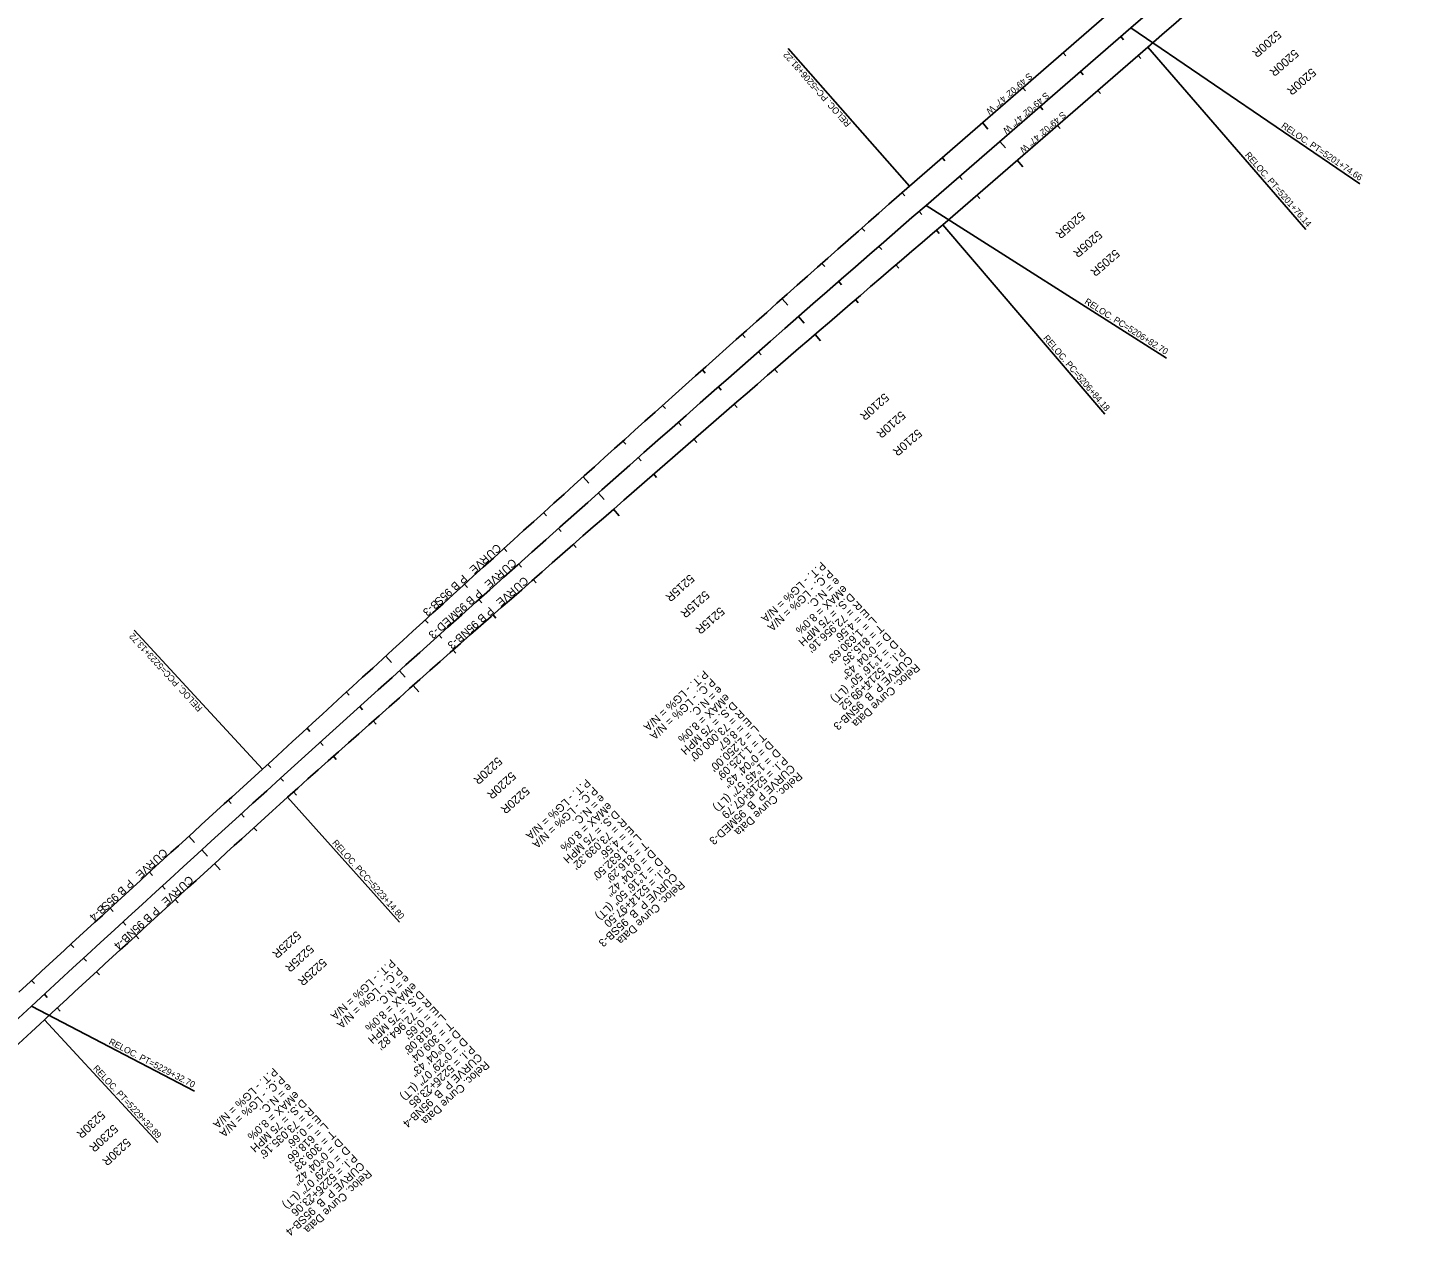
# Model space of a CAD drawing. Extents: x 2161211 to 2175594, y 601812 to 617732.
# Drawn here: x 2167933 to 2170529, y 609442 to 611719 of the extents above; entities that cross this region are included whole.
import ezdxf

# ---------------------------------------------------------------- set-up
doc = ezdxf.new("R2010")
doc.units = 0
for name, color, linetype in [('RD_HC_CL_Rel', 7, 'Continuous'), ('RD_HC_Data_Rel', 7, 'Continuous'), ('RD_HC_Data_Tic_Rel', 7, 'Continuous'), ('RD_HC_TX_Rel_Sta50', 7, 'Continuous')]:
    doc.layers.add(name, color=color, linetype=linetype)

msp = doc.modelspace()

# ---------------------------------------------------------------- linework, layer by layer
at = {"layer": 'RD_HC_CL_Rel'}
for p, q in [((2169968.3, 611754.8), (2169584.6, 611421.8)), ((2169999.7, 611718.5), (2169616.1, 611385.5)), ((2170031.2, 611682.3), (2169647.5, 611349.3)), ((2167939.8, 609884.8), (2165490.6, 607623.3)), ((2167963.7, 609859.1), (2165514.5, 607597.4))]:
    msp.add_line(p, q, dxfattribs=at)
for centre, radius, start, end in [((2122152.2, 666851.2), 73000, 310.953509, 312.719474), ((2122152.2, 666851.2), 73048, 310.953509, 312.719474), ((2217890.3, 556637.7), 73039.3, 131.404137, 132.684757), ((2217463.6, 556252.9), 73000, 130.953509, 132.719474), ((2217031.5, 555875.3), 72956.2, 130.502821, 131.783426), ((2217463.6, 556252.9), 73035.2, 132.23405, 132.719387), ((2217463.6, 556252.9), 72964.8, 132.234034, 132.719387)]:
    msp.add_arc(centre, radius, start, end, dxfattribs=at)
at = {"layer": 'RD_HC_Data_Rel'}
for p, q in [((2169999.7, 611718.5), (2170428.7, 611426.1)), ((2169584.6, 611421.8), (2169357.3, 611679.5)), ((2170031.2, 611682.3), (2170327.7, 611340.6)), ((2169616.1, 611385.5), (2170066.3, 611099.2)), ((2169647.5, 611349.3), (2169950.9, 610994.1)), ((2168372.3, 610328.5), (2168131.9, 610589.1)), ((2168419.6, 610276.4), (2168628.9, 610042.2)), ((2167939.8, 609884.8), (2168244.9, 609725.3)), ((2167963.7, 609859.1), (2168176.1, 609629.1))]:
    msp.add_line(p, q, dxfattribs=at)
at = {"layer": 'RD_HC_Data_Tic_Rel'}
for p, q in [((2169980.6, 611701.9), (2169985.9, 611695.9)), ((2169872.5, 611671.6), (2169877.8, 611665.6)), ((2170013.2, 611666.6), (2170018.4, 611660.6)), ((2169905.1, 611636.4), (2169910.3, 611630.3)), ((2169797, 611606.1), (2169802.2, 611600.1)), ((2169937.7, 611601.1), (2169942.9, 611595)), ((2169829.6, 611570.8), (2169834.8, 611564.8)), ((2169721.5, 611540.6), (2169731.9, 611528.5)), ((2169862.1, 611535.5), (2169867.4, 611529.5)), ((2169754, 611505.3), (2169764.5, 611493.2)), ((2169645.9, 611475), (2169651.2, 611469)), ((2169786.6, 611470), (2169797.1, 611457.9)), ((2169678.5, 611439.7), (2169683.8, 611433.7)), ((2169570.5, 611409.4), (2169575.8, 611403.4)), ((2169711.1, 611404.4), (2169716.3, 611398.4)), ((2169603, 611374.2), (2169608.2, 611368.1)), ((2169495.6, 611343.1), (2169500.9, 611337.2)), ((2169635.5, 611339), (2169640.7, 611332.9)), ((2169527.5, 611308.6), (2169532.8, 611302.5)), ((2169420.7, 611276.8), (2169426, 611270.9)), ((2169559.5, 611274), (2169564.7, 611267.9)), ((2169452.2, 611242.9), (2169457.4, 611236.8)), ((2169346, 611210.4), (2169356.6, 611198.5)), ((2169483.6, 611208.9), (2169488.8, 611202.8)), ((2169376.9, 611177), (2169387.4, 611165)), ((2169271.3, 611143.9), (2169276.6, 611137.9)), ((2169407.8, 611143.6), (2169418.3, 611131.5)), ((2169301.7, 611111.1), (2169307, 611105.1)), ((2169196.7, 611077.3), (2169202, 611071.3)), ((2169332.1, 611078.3), (2169337.3, 611072.3)), ((2169226.6, 611045.1), (2169231.9, 611039.1)), ((2169122.2, 611010.6), (2169127.6, 611004.6)), ((2169256.5, 611012.9), (2169261.7, 611006.8)), ((2169151.6, 610979), (2169156.9, 610973)), ((2169047.8, 610943.8), (2169053.2, 610937.8)), ((2169181, 610947.3), (2169186.2, 610941.3)), ((2169076.6, 610912.7), (2169081.9, 610906.7)), ((2168973.5, 610876.8), (2168984.2, 610865)), ((2169105.5, 610881.7), (2169110.8, 610875.7)), ((2169001.8, 610846.4), (2169012.4, 610834.4)), ((2168899.3, 610809.8), (2168904.7, 610803.9)), ((2169030.2, 610816), (2169040.7, 610803.9)), ((2168927.1, 610779.9), (2168932.4, 610774)), ((2168825.2, 610742.7), (2168830.5, 610736.8)), ((2168954.9, 610750.1), (2168960.2, 610744.1)), ((2168852.4, 610713.4), (2168857.7, 610707.4)), ((2168879.7, 610684.2), (2168885, 610678.1)), ((2168751.1, 610675.5), (2168756.5, 610669.5)), ((2168777.9, 610646.8), (2168783.2, 610640.8)), ((2168677.2, 610608.1), (2168682.6, 610602.2)), ((2168804.7, 610618.1), (2168809.9, 610612.1)), ((2168703.4, 610580), (2168708.7, 610574.1)), ((2168729.7, 610551.9), (2168735, 610546)), ((2168603.4, 610540.7), (2168614.2, 610528.9)), ((2168629, 610513.2), (2168639.7, 610501.3)), ((2168529.6, 610473.2), (2168535, 610467.3)), ((2168654.8, 610485.7), (2168665.4, 610473.7)), ((2168554.7, 610446.2), (2168560.1, 610440.3)), ((2168580, 610419.3), (2168585.3, 610413.3)), ((2168455.9, 610405.5), (2168461.4, 610399.6)), ((2168480.5, 610379.2), (2168485.9, 610373.2)), ((2168505.2, 610352.9), (2168510.6, 610346.9)), ((2168382.4, 610337.8), (2168387.8, 610331.9)), ((2168406.4, 610312), (2168411.8, 610306.1)), ((2168308.4, 610270.5), (2168313.8, 610264.6)), ((2168430.6, 610286.3), (2168435.9, 610280.3)), ((2168332.4, 610244.8), (2168337.8, 610238.9)), ((2168356.5, 610219.1), (2168361.9, 610213.2)), ((2168234.5, 610203.1), (2168245.3, 610191.3)), ((2168258.5, 610177.4), (2168269.3, 610165.6)), ((2168160.7, 610135.7), (2168166.1, 610129.8)), ((2168282.6, 610151.8), (2168293.4, 610140)), ((2168184.7, 610110), (2168190.1, 610104.1)), ((2168208.8, 610084.3), (2168214.2, 610078.4)), ((2168087, 610068.1), (2168092.4, 610062.2)), ((2168111, 610042.4), (2168116.4, 610036.5)), ((2168135.1, 610016.8), (2168140.5, 610010.9)), ((2168013.3, 610000.4), (2168018.7, 609994.6)), ((2168037.3, 609974.8), (2168042.7, 609968.9)), ((2167939.8, 609932.7), (2167945.2, 609926.8)), ((2168061.4, 609949.1), (2168066.8, 609943.2)), ((2167963.8, 609907), (2167969.2, 609901.1)), ((2167987.9, 609881.4), (2167993.3, 609875.5))]:
    msp.add_line(p, q, dxfattribs=at)

# ---------------------------------------------------------------- texts
at = {"layer": 'RD_HC_Data_Rel'}
for s, height, rotation, p in [('RELOC. PC=5206+81.22', 12, 131.4041, (2169475.8, 611539.1)), ('S 49°02\' 47" W', 12, 220.9535, (2169808.6, 611634.7)), ('S 49°02\' 47" W', 12, 220.9535, (2169840.1, 611598.5)), ('S 49°02\' 47" W', 12, 220.9535, (2169871.6, 611562.2)), ('RELOC. PT=5201+74.66', 12, 325.7115, (2170280.4, 611532)), ('RELOC. PT=5201+76.14', 12, 310.9535, (2170212.6, 611479.3)), ('RELOC. PC=5206+82.70', 12, 327.544, (2169911.7, 611202.2)), ('RELOC. PC=5206+84.18', 12, 310.5028, (2169834.7, 611136.3)), ('R', 15, 222.236, (2168788.7, 610731.9)), ('U', 15, 222.2235, (2168800.5, 610742.6)), ('C', 15, 222.212, (2168811.4, 610752.4)), ('E', 15, 222.2571, (2168768.8, 610713.8)), ('V', 15, 222.2465, (2168778.7, 610722.8)), ('U', 15, 221.7706, (2168829.2, 610714.8)), ('C', 15, 221.759, (2168840.2, 610724.6)), ('P.T. - LG% = N/A', 15, 222.7195, (2169419.8, 610718.7)), ('B', 15, 222.2943, (2168733.7, 610681.9)), ('P', 15, 222.2794, (2168747.7, 610694.6)), ('E', 15, 221.8042, (2168797.3, 610686.3)), ('V', 15, 221.7936, (2168807.3, 610695.2)), ('R', 15, 221.7831, (2168817.4, 610704.2)), ('U', 15, 221.3246, (2168851.4, 610681.2)), ('C', 15, 221.313, (2168862.5, 610690.9)), ('P.C. - LG% = N/A', 15, 222.7195, (2169433.4, 610704)), ('e = N.C.', 15, 222.7195, (2169446.9, 610689.3)), ('S', 15, 222.3265, (2168703.3, 610654.2)), ('5', 15, 222.3178, (2168711.5, 610661.7)), ('9', 15, 222.3092, (2168719.6, 610669.1)), ('B', 15, 221.8414, (2168761.9, 610654.6)), ('P', 15, 221.8265, (2168776.1, 610667.3)), ('V', 15, 221.3476, (2168829.4, 610661.8)), ('R', 15, 221.3371, (2168839.5, 610670.7)), ('eMAX = 8.0%', 15, 222.7195, (2169460.5, 610674.6)), ('D.S. = 75 MPH', 15, 222.7195, (2169474.1, 610659.9)), ('3', 15, 222.3514, (2168679.8, 610632.8)), ('-', 15, 222.3457, (2168685.2, 610637.8)), ('B', 15, 222.3351, (2168695.2, 610646.8)), ('M', 15, 221.8736, (2168731.4, 610627.3)), ('5', 15, 221.865, (2168739.6, 610634.6)), ('9', 15, 221.8563, (2168747.8, 610642)), ('P', 15, 221.3806, (2168797.9, 610634.1)), ('E', 15, 221.3582, (2168819.2, 610652.9)), ("R = 72,956.16'", 15, 222.7195, (2169487.6, 610645.3)), ("E = 4.56'", 15, 222.7195, (2169501.2, 610630.6)), ('D', 15, 221.8986, (2168707.7, 610606)), ('E', 15, 221.888, (2168717.7, 610615)), ('9', 15, 221.4104, (2168769.4, 610609)), ('B', 15, 221.3955, (2168783.6, 610621.6)), ("L = 1,630.63'", 15, 222.7195, (2169514.8, 610615.9)), ('RELOC. PCC=5223+13.72', 12, 132.6848, (2168260.9, 610443.4)), ('3', 15, 221.9168, (2168690.4, 610590.5)), ('-', 15, 221.9111, (2168695.8, 610595.4)), ('B', 15, 221.4392, (2168741.8, 610584.7)), ('N', 15, 221.4277, (2168752.9, 610594.5)), ('5', 15, 221.419, (2168761.1, 610601.7)), ("T = 815.35'", 15, 222.7195, (2169528.3, 610601.2)), ('D = 0°04\' 43"', 15, 222.7195, (2169541.9, 610586.5)), ('3', 15, 221.4556, (2168726.3, 610571)), ('-', 15, 221.4498, (2168731.8, 610575.8)), ('    = 1°16\' 50" (LT)', 15, 222.7195, (2169555.5, 610571.8)), ('P.I. = 5214+99.52', 15, 222.7195, (2169569.1, 610557.1)), ('D', 15, 222.7195, (2169555.5, 610571.8)), ('CURVE P_B_95NB-3', 15, 222.7195, (2169582.6, 610542.4)), ('Reloc. Curve Data', 15, 222.7195, (2169596.2, 610527.7)), ('P.T. - LG% = N/A', 15, 222.7195, (2169199.4, 610515.2)), ('P.C. - LG% = N/A', 15, 222.7195, (2169213, 610500.5)), ('e = N.C.', 15, 222.7195, (2169226.5, 610485.8)), ('eMAX = 8.0%', 15, 222.7195, (2169240.1, 610471.1)), ('D.S. = 75 MPH', 15, 222.7195, (2169253.7, 610456.4)), ("R = 73,000.00'", 15, 222.7195, (2169267.2, 610441.7)), ("E = 8.67'", 15, 222.7195, (2169280.8, 610427)), ("L = 2,250.00'", 15, 222.7195, (2169294.4, 610412.3)), ("T = 1,125.09'", 15, 222.7195, (2169307.9, 610397.6)), ('D = 0°04\' 43"', 15, 222.7195, (2169321.5, 610383)), ('D', 15, 222.7195, (2169335.1, 610368.3)), ('    = 1°45\' 57" (LT)', 15, 222.7195, (2169335.1, 610368.3)), ('P.I. = 5218+07.79', 15, 222.7195, (2169348.6, 610353.6)), ('CURVE P_B_95MED-3', 15, 222.7195, (2169362.2, 610338.9)), ('Reloc. Curve Data', 15, 222.7195, (2169375.8, 610324.2)), ('P.T. - LG% = N/A', 15, 222.7195, (2168979, 610311.7)), ('P.C. - LG% = N/A', 15, 222.7195, (2168992.6, 610297)), ('eMAX = 8.0%', 15, 222.7195, (2169019.7, 610267.6)), ('e = N.C.', 15, 222.7195, (2169006.1, 610282.3)), ('D.S. = 75 MPH', 15, 222.7195, (2169033.3, 610252.9)), ("R = 73,039.32'", 15, 222.7195, (2169046.8, 610238.2)), ("E = 4.56'", 15, 222.7195, (2169060.4, 610223.5)), ('RELOC. PCC=5223+14.80', 12, 311.7834, (2168502.2, 610190)), ("L = 1,632.50'", 15, 222.7195, (2169074, 610208.8)), ("T = 816.29'", 15, 222.7195, (2169087.5, 610194.1)), ('R', 15, 222.4495, (2168163.6, 610160.6)), ('U', 15, 222.437, (2168175.3, 610171.4)), ('C', 15, 222.4255, (2168186.2, 610181.3)), ('D = 0°04\' 42"', 15, 222.7195, (2169101.1, 610179.4)), ('D', 15, 222.7195, (2169114.7, 610164.7)), ('E', 15, 222.4706, (2168143.7, 610142.5)), ('V', 15, 222.4601, (2168153.6, 610151.5)), ('    = 1°16\' 50" (LT)', 15, 222.7195, (2169114.7, 610164.7)), ('P.I. = 5214+97.50', 15, 222.7195, (2169128.2, 610150)), ('B', 15, 222.5079, (2168108.7, 610110.4)), ('P', 15, 222.493, (2168122.7, 610123.2)), ('R', 15, 222.4485, (2168212, 610109.6)), ('U', 15, 222.436, (2168223.7, 610120.4)), ('C', 15, 222.4245, (2168234.6, 610130.3)), ('CURVE P_B_95SB-3', 15, 222.7195, (2169141.8, 610135.4)), ('Reloc. Curve Data', 15, 222.7195, (2169155.4, 610120.7)), ('S', 15, 222.54, (2168078.5, 610082.7)), ('5', 15, 222.5314, (2168086.6, 610090.1)), ('9', 15, 222.5227, (2168094.7, 610097.6)), ('E', 15, 222.4696, (2168192.1, 610091.4)), ('V', 15, 222.4591, (2168202.1, 610100.5)), ('4', 15, 222.565, (2168055, 610061.2)), ('-', 15, 222.5592, (2168060.4, 610066.1)), ('B', 15, 222.5487, (2168070.3, 610075.2)), ('B', 15, 222.5069, (2168157.1, 610059.4)), ('P', 15, 222.492, (2168171.1, 610072.2)), ('N', 15, 222.5391, (2168126.9, 610031.7)), ('5', 15, 222.5304, (2168135, 610039.1)), ('9', 15, 222.5218, (2168143.1, 610046.6)), ('4', 15, 222.567, (2168100.7, 610007.7)), ('-', 15, 222.5612, (2168106.1, 610012.6)), ('B', 15, 222.5506, (2168116.1, 610021.7)), ('P.T. - LG% = N/A', 15, 222.7195, (2168613.1, 609973.8)), ('P.C. - LG% = N/A', 15, 222.7195, (2168626.6, 609959.1)), ('eMAX = 8.0%', 15, 222.7195, (2168653.8, 609929.7)), ('e = N.C.', 15, 222.7195, (2168640.2, 609944.4)), ('D.S. = 75 MPH', 15, 222.7195, (2168667.3, 609915)), ("R = 72,964.82'", 15, 222.7195, (2168680.9, 609900.3)), ("E = 0.65'", 15, 222.7195, (2168694.5, 609885.6)), ("L = 618.08'", 15, 222.7195, (2168708, 609870.9)), ("T = 309.04'", 15, 222.7195, (2168721.6, 609856.2)), ('RELOC. PT=5229+32.70', 12, 332.4012, (2168083.4, 609814.2)), ('D = 0°04\' 43"', 15, 222.7195, (2168735.2, 609841.5)), ('D', 15, 222.7195, (2168748.7, 609826.8)), ('    = 0°29\' 07" (LT)', 15, 222.7195, (2168748.7, 609826.8)), ('P.I. = 5226+23.85', 15, 222.7195, (2168762.3, 609812.1)), ('RELOC. PT=5229+32.89', 12, 312.7194, (2168054, 609767.2)), ('CURVE P_B_95NB-4', 15, 222.7195, (2168775.9, 609797.5)), ('Reloc. Curve Data', 15, 222.7195, (2168789.5, 609782.8)), ('P.T. - LG% = N/A', 15, 222.7195, (2168392.7, 609770.3)), ('P.C. - LG% = N/A', 15, 222.7195, (2168406.2, 609755.6)), ('eMAX = 8.0%', 15, 222.7195, (2168433.4, 609726.2)), ('e = N.C.', 15, 222.7195, (2168419.8, 609740.9)), ('D.S. = 75 MPH', 15, 222.7195, (2168446.9, 609711.5)), ("R = 73,035.16'", 15, 222.7195, (2168460.5, 609696.8)), ("L = 618.66'", 15, 222.7195, (2168487.6, 609667.4)), ("E = 0.66'", 15, 222.7195, (2168474.1, 609682.1)), ("T = 309.33'", 15, 222.7195, (2168501.2, 609652.7)), ('D = 0°04\' 42"', 15, 222.7195, (2168514.8, 609638)), ('D', 15, 222.7195, (2168528.3, 609623.3)), ('    = 0°29\' 07" (LT)', 15, 222.7195, (2168528.3, 609623.3)), ('CURVE P_B_95SB-4', 15, 222.7195, (2168555.5, 609593.9)), ('P.I. = 5226+23.06', 15, 222.7195, (2168541.9, 609608.6)), ('Reloc. Curve Data', 15, 222.7195, (2168569, 609579.2))]:
    msp.add_text(s, height=height, rotation=rotation, dxfattribs=at).set_placement(p)
at = {"layer": 'RD_HC_TX_Rel_Sta50'}
for s, rotation, p in [('5200R', 221.0895, (2170272.9, 611714.5)), ('5200R', 221.0906, (2170305.5, 611679.2)), ('5200R', 221.0917, (2170338.1, 611643.9)), ('5205R', 220.9535, (2169904.9, 611374.8)), ('5205R', 220.9535, (2169937.5, 611339.5)), ('5205R', 220.9535, (2169970.1, 611304.3)), ('5210R', 221.6542, (2169537.8, 611034.7)), ('5210R', 221.2026, (2169568.8, 611001.1)), ('5210R', 220.7509, (2169599.8, 610967.4)), ('5215R', 222.0464, (2169173, 610695.2)), ('5215R', 221.595, (2169201.4, 610664.5)), ('5215R', 221.1435, (2169229.8, 610633.8)), ('5220R', 222.4387, (2168812.8, 610352.9)), ('5220R', 221.9874, (2168838.6, 610325.1)), ('5220R', 221.5362, (2168864.4, 610297.3)), ('5225R', 222.3802, (2168435.9, 610026.8)), ('5225R', 222.3799, (2168459.9, 610001.1)), ('5225R', 222.3795, (2168484, 609975.5)), ('5230R', 222.7194, (2168068.8, 609689.7)), ('5230R', 222.7195, (2168092.8, 609664)), ('5230R', 222.7194, (2168116.8, 609638.4))]:
    msp.add_text(s, height=16, rotation=rotation, dxfattribs=at).set_placement(p)

doc.saveas('drawing.dxf')
